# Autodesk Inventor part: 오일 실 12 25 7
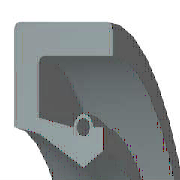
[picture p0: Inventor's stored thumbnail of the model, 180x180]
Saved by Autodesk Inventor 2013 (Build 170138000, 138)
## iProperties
IsCustomPart: 1
Created: 2012-02
Part Number: 오일 실 12 25 7
Material: 고무
Description: 오일-실
Document SubType Name: Modeling
Standard: KS B 2804
Designer: mduedu
Standards Organization: KS
Language: ko-KR
Size Designation: S - 12 25 7
Categories: <MemberInstance><Categories><Category DisplayName="샤프트 부품" InternalName="7f7aeb1f-a693-4053-b835-cee3144e0d98" Mnemonic="SHFT"><Category DisplayName="실링" Intern
Density: 0.93 g/cm^3
Mass: 1.26338 g
Surface Area: 20.8889 cm^2
Volume: 1.35847 cm^3
Author: mduedu
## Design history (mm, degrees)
revolve "본체" stored, may be unused: angle "d17" = 90 deg
revolve "스프링1" stored, may be unused: angle "d18" = 90 deg
body "Solid1"
sketch "스케치1"
  geometry: L1 (0, 12.5)-(7, 12.5); L2 (7, 12.5)-(7, 11.25); L3 (7, 11.25)-(1.75, 11.25); L4 (0, 12.5)-(0, 8.1); L5 (0, 8.1)-(1.75, 7.75); L6 (1.75, 7.75)-(4.9, 6); L7 (4.9, 6)-(0, 6); L8 (6.3, 6.875)-(6.3, 8.1); L9 (0, 0)-(9.586, 0) reference; L10 (4.9, 6)-(6.3, 6.875); L11 (0, 18)-(0, -3) reference; L12 (-1.917, 0)-(11.503, 0) reference; L13 (4.2, 8.1)-(1.75, 8.59); L14 (1.75, 8.59)-(1.75, 11.25); L15 (6.3, 8.1)-(5.6, 8.1); C1 r 0.455 at (4.9, 8.1); A1 r 0.7 centre (4.9, 8.1) between (5.6, 8.1) and (4.2, 8.1)
  constraints: 26 end point, 5 horizontal alignment, 4 perpendicular, 2 centre point, 2 collinear, 2 horizontal, 2 parallel, 2 point on circle, 2 point on line, 2 vertical alignment, 1 coincident
  dimensions: "d0" = 25 diameter of L1 L9 (= SD2); "d1" = 13.75 diameter of L8.start L9 (= ABDM); "d2" = 1.25 distance of L1.end L2.end (computed from SD); "d3" = 0.91 diameter of C1 (= SPDI); "d4" = 1.4 diameter of A1 (= SPDA); "d5" = 12 diameter of L6.end L9 (= NND); "d6" = 15.5 diameter of L5.end L9 (= TKDM); "d7" = 16.2 diameter of L4.end L9 (= HLDM); "d8" = 4.9 distance from line of C1.centre L4 (= SPDST); "d9" = 6.3 distance between parallel lines of L8 L4 (= SDI); "d10" = 7 distance between parallel lines of L2 L4 (= SWDT); "d12" = 1.75 distance between parallel lines of L14 L4 (= SD)
fillet "모깎기1" dims "d11" = 0.3 (= RR)
other parameters: "SD2" = 25 [user parameter; used in 1 equation term], "SWDT" = 7 [user parameter; used in 1 equation term], "RR" = 0.3 [user parameter; used in 1 equation term], "SD" = 1.75 [user parameter; used in 2 equation terms], "NND" = 12 [user parameter; used in 1 equation term], "SPDA" = 1.4 [user parameter; used in 1 equation term], "SPDI" = 0.91 [user parameter; used in 1 equation term], "TKDM" = 15.5 [user parameter; used in 1 equation term], "HLDM" = 16.2 [user parameter; used in 1 equation term], "ABDM" = 13.75 [user parameter; used in 1 equation term], "SDI" = 6.3 [user parameter; used in 1 equation term], "SPDST" = 4.9 [user parameter; used in 1 equation term], "d13" = 0, "d14" = 0, "d15" = 0, "LAB" = 0.35 [user parameter]
